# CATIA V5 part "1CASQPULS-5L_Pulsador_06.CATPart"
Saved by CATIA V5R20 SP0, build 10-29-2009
Part number: 1CASQPULS-5L_Pulsador_06
Revision: ANY
Definition: UNKNOWN
Nomenclature: 1CASQPULS-5L_Pulsador_06
Source: Unknown
Bounding box of the stored display mesh (mm): x -6.142 to 6.142, y 0 to 15.3, z -6.3 to 6.3
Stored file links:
  C:\Users\Utente\Desktop\IO LAVORO\3D X SITO CF\CUMSA\3D files AE\AE 052430\1CASQPULS-5L_Pulsador_06.CATPart
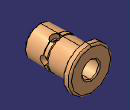
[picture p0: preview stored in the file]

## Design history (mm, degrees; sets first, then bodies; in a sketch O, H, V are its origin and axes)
Body1 "MatrizC1" (main body)
  Solid1: solid without history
